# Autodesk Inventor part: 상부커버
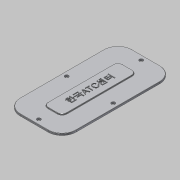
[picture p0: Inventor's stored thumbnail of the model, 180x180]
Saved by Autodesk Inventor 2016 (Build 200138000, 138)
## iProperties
Created: 2016-02
Part Number: 상부커버
Material: 알루미늄 6061
Document SubType Name: Modeling
Designer: mduedu
Density: 2.71 g/cm^3
Mass: 42.0587 g
Surface Area: 149.263 cm^2
Volume: 15.5198 cm^3
Appearance: 알루미늄 - 평지
Author: mduedu
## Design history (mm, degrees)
sketch "스케치1"
  geometry: L1 (30, 60)-(-30, 60); L2 (-30, 60)-(-30, -60); L3 (-30, -60)-(30, -60); L4 (30, -60)-(30, 60); L5 (30, 60)-(-30, -60); L6 (-30, 60)-(30, -60); 1 further point
  constraints: 12 end point, 2 midpoint, 2 parallel, 1 horizontal, 1 perpendicular
  dimensions: "d0" = 60 distance of L2.end L3.end; "d2" = 120 distance of L1.end L2.end
extrude "돌출1" new body sketch "스케치1" distance "d3" = 2; taper "d4" = 0 deg
fillet "모깎기1" dims "d5" = 15
sketch "스케치2"
  geometry: L1 (30, 45)-(30, -45) reference; L2 (15, -60)-(-15, -60) reference; L3 (-30, -45)-(-30, 45) reference; L4 (-15, 60)-(15, 60) reference; L5 (25, 45)-(25, -45); L6 (15, -55)-(-15, -55); L7 (-25, -45)-(-25, 45); L8 (-15, 55)-(15, 55); A1 r 15 centre (15, 45) between (30, 45) and (15, 60) reference; A2 r 15 centre (15, -45) between (15, -60) and (30, -45) reference; A3 r 15 centre (-15, -45) between (-30, -45) and (-15, -60) reference; A4 r 15 centre (-15, 45) between (-15, 60) and (-30, 45) reference; A5 r 10 centre (15, 45) between (25, 45) and (15, 55); A6 r 10 centre (15, -45) between (15, -55) and (25, -45); A7 r 10 centre (-15, -45) between (-25, -45) and (-15, -55); A8 r 10 centre (-15, 45) between (-15, 55) and (-25, 45); 4 further points
  constraints: 8 end point, 8 point on circle, 4 centre point, 4 midpoint, 7 other
  dimensions: "d8" = 5 distance between parallel lines of L7 L3
hole "구멍1" sketch "스케치2" at (0, 55), (25, 0), (0, -55), (-25, 0) diameter "d9" = 4; stored, may be unused: countersink angle "d13" = 90 deg, drill point angle "d15" = 118 deg; dims "d10" = 6, "d11" = 4, "d12" = 2, "d14" = 8
sketch "스케치3"
  geometry: L1 (10, -40)-(-10, -40); L2 (-10, -40)-(-10, 40); L3 (-10, 40)-(10, 40); L4 (10, 40)-(10, -40); L5 (10, -40)-(-10, 40); L6 (-10, -40)-(10, 40); 1 further point
  constraints: 12 end point, 2 midpoint, 2 parallel, 1 horizontal, 1 perpendicular
  dimensions: "d16" = 80 distance of L1.end L2.end; "d18" = 20 distance of L2.end L3.end
extrude "돌출2" join sketch "스케치3" distance "d19" = 1; taper "d20" = 0 deg
fillet "모깎기2" dims "d21" = 5
fillet "모깎기3" dims "d22" = 0.3
fillet "모깎기4" dims "d23" = 0.3
sketch "스케치4"
  geometry: 2 further points
  constraints: 1 coincident, 1 other
feature "엠보싱1" sketch "스케치4" dims "d0" = 60, "d2" = 120, "d8" = 5, "d24" = 0.5, "d25" = 0
node "솔리드1"
node "절단 모서리 투영1"
